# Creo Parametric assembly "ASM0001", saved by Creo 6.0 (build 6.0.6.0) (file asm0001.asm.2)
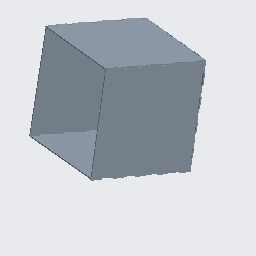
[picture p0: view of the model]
Units: Inch lbm Second (Pro/E Default); INCH, POUND, SECS

Created from: INLBS_ASM_DESIGN.ASM

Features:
  1. datum plane "ASM_RIGHT"
  2. datum plane "ASM_TOP"
  3. datum plane "ASM_FRONT"
  4. coordinate system
  5. component "PRT0001"
  6. component "LEFT"
  7. coordinate system
  8. component "BACK"
  9. component "PRT0002"
  10. component "RIGHT"

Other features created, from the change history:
  component "BACK.PRT"
  component "RIGHT.PRT"
  component "PRT0002.PRT"

Other named items: ACS4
